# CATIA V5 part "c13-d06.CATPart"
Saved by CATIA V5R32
Part number: Part1
Bounding box of the stored display mesh (mm): x -40 to 40, y -65 to 65, z 0 to 15
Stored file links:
  D:\PROJECTS\Project 2022\CATIA V5 6R 2022\Resources\Part Files\c13_catia_v5_6r2022_prt\c13_catia_v5-6r2022_figr_13-21\c13-d06.CATPart
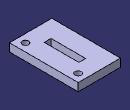
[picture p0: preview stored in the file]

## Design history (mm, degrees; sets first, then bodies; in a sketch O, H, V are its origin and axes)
Body1 (main body)
  Sketch1 on xy-plane, origin (0, 0, 0), H (1, 0, 0), V (0, 1, 0)
    line L1 (40, 65) -> (40, -65)
    line L2 (40, -65) -> (-40, -65)
    line L3 (-40, -65) -> (-40, 65)
    line L4 (-40, 65) -> (40, 65)
    length L1 = 130
    length L2 = 80
    vertical: L1 V, L3 V
    horizontal: L2 H, L4 H
    equidistance: L1 L3 O, L2 L4 O
  Pad1: profile Sketch1, direction (0, 0, 1), length 15
  Sketch2 on face of Pad1, origin (0, 0, 15), H (1, 0, 0), V (0, 1, 0)
    line L1 (6.4019, 32.7538) -> (6.4019, -32.7538)
    line L2 (6.4019, -32.7538) -> (-6.4019, -32.7538)
    line L3 (-6.4019, -32.7538) -> (-6.4019, 32.7538)
    line L4 (-6.4019, 32.7538) -> (6.4019, 32.7538)
    vertical: L1 V, L3 V
    horizontal: L2 H, L4 H
    equidistance: L1 L3 O, L2 L4 O
  Pocket1: profile Sketch2, direction (0, 0, -1), through (limit type 3)
  Sketch3 on face of Pad1, origin (30.5043, -33.5377, 15), H (1, 0, 0), V (0, 1, 0)
    point P1 (-5.5043, -16.4623)
    reference projected line E1 (9.4957, -31.4623) -> (9.4957, 98.5377) from edge [face of Pad1 | face of Pad1]
    reference projected line E2 (-70.5043, -31.4623) -> (9.4957, -31.4623) from edge [face of Pad1 | face of Pad1]
    distance P1 E1 = 15
    distance P1 E2 = 15
  Hole1: placed by Sketch3, at (25, -50, 15) direction (0, 0, -1), diameter 12, through (limit type 3)
  Mirror1: of Hole1, about zx-plane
